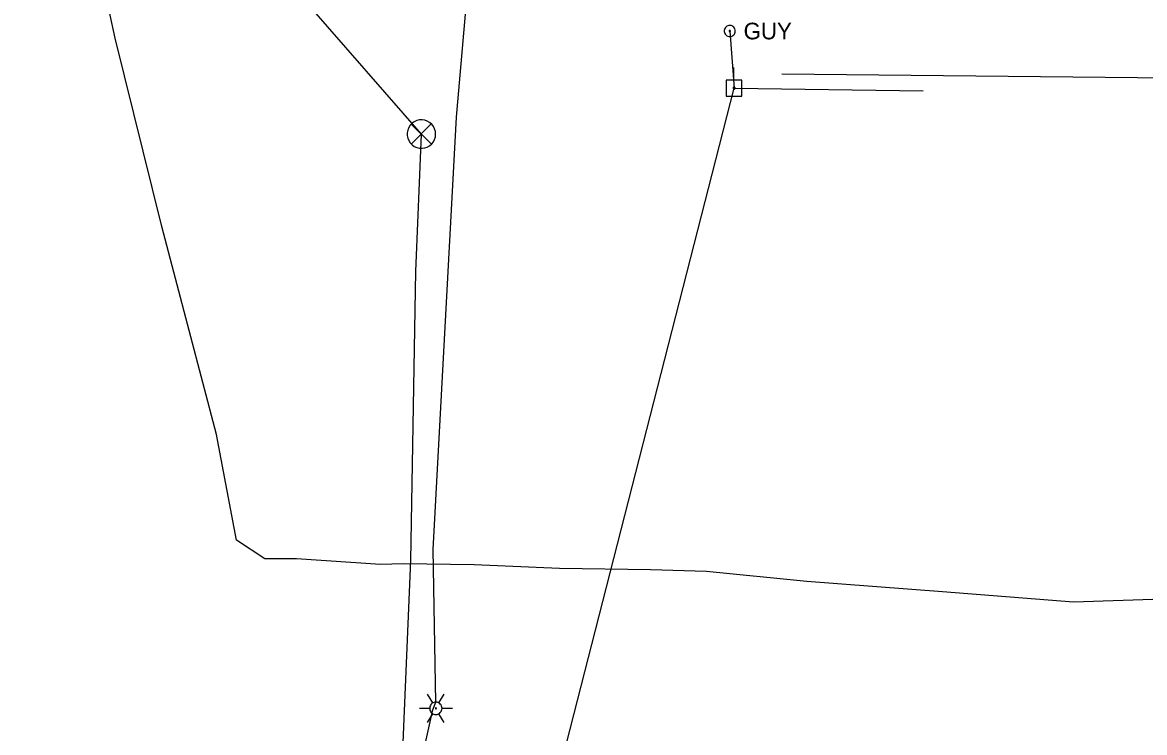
# Model space of a CAD drawing. Extents: x 596028 to 606371, y 330010 to 403088.
# Drawn here: x 604376.9 to 604636.4, y 338862.5 to 339026.7 of the extents above; entities that cross this region are included whole.
import ezdxf

# ---------------------------------------------------------------- set-up
doc = ezdxf.new("R2010")
doc.units = 0
for name, color, linetype in [('E_FTMS', 7, 'Continuous'), ('E_FTMS_Conduit', 7, 'Continuous'), ('E_LTG', 7, 'Continuous'), ('E_LTG_CID', 7, 'Continuous'), ('E_UTL_EGuyWire', 7, 'Continuous'), ('E_UTL_EPowerPole', 7, 'Continuous'), ('E_UTL_FO_UG_MWFN', 7, 'Continuous'), ('E_UTL_Overhead', 7, 'Continuous'), ('E_UTL_T_UG', 7, 'Continuous')]:
    doc.layers.add(name, color=color, linetype=linetype)

msp = doc.modelspace()

# ---------------------------------------------------------------- linework, layer by layer
at = {"layer": 'E_FTMS'}
for points in [[(604472.47, 339000.91), (604472.41, 339001.53), (604472.23, 339002.14), (604471.94, 339002.69), (604471.56, 339003.19), (604471.08, 339003.6), (604470.54, 339003.91), (604469.95, 339004.12), (604469.33, 339004.21), (604468.7, 339004.18), (604468.09, 339004.03), (604467.52, 339003.77), (604467.01, 339003.4), (604466.57, 339002.95), (604466.23, 339002.42), (604466, 339001.84), (604465.88, 339001.22), (604465.88, 339000.6), (604466, 338999.98), (604466.23, 338999.4), (604466.57, 338998.87), (604467.01, 338998.42), (604467.52, 338998.05), (604468.09, 338997.79), (604468.7, 338997.64), (604469.33, 338997.61), (604469.95, 338997.7), (604470.54, 338997.91), (604471.08, 338998.22), (604471.56, 338998.63), (604471.94, 338999.12), (604472.23, 338999.68), (604472.41, 339000.28), (604472.47, 339000.91)], [(604471.43, 339003.24), (604466.82, 338998.59)], [(604466.82, 339003.2), (604471.47, 338998.54)]]:
    msp.add_lwpolyline(points, dxfattribs=at)
at = {"layer": 'E_FTMS_Conduit'}
msp.add_lwpolyline([(604482.26, 338261.55), (604473.93, 338334.41), (604464.29, 338400.61), (604460.79, 338428.69), (604454.21, 338489.14), (604450.76, 338535.77), (604450.59, 338564.2), (604449.65, 338594.55), (604451.53, 338620.45), (604457.08, 338705.91), (604458.98, 338757.42), (604459.6, 338770.85), (604464.03, 338838.22), (604466.7, 338902.27), (604467.92, 338969.11), (604469.17, 339000.91), (604443.18, 339030.65), (604422.51, 339055.17), (604397.22, 339086.29), (604379.91, 339100.81)], dxfattribs=at)
at = {"layer": 'E_LTG'}
for points in [[(604471.8, 338869.35), (604470.61, 338871.41)], [(604473.23, 338869.35), (604474.42, 338871.41)], [(604468.71, 338868.11), (604471.09, 338868.11)], [(604473.95, 338868.11), (604473.92, 338868.38), (604473.84, 338868.64), (604473.72, 338868.88), (604473.55, 338869.09), (604473.35, 338869.27), (604473.11, 338869.41), (604472.85, 338869.5), (604472.59, 338869.54), (604472.31, 338869.52), (604472.05, 338869.46), (604471.8, 338869.35), (604471.58, 338869.19), (604471.39, 338868.99), (604471.25, 338868.76), (604471.15, 338868.51), (604471.1, 338868.24), (604471.1, 338867.97), (604471.15, 338867.71), (604471.25, 338867.45), (604471.39, 338867.22), (604471.58, 338867.03), (604471.8, 338866.87), (604472.05, 338866.76), (604472.31, 338866.69), (604472.59, 338866.68), (604472.85, 338866.72), (604473.11, 338866.81), (604473.35, 338866.94), (604473.55, 338867.12), (604473.72, 338867.34), (604473.84, 338867.58), (604473.92, 338867.84), (604473.95, 338868.11)], [(604473.95, 338868.11), (604473.92, 338868.38), (604473.84, 338868.64), (604473.72, 338868.88), (604473.55, 338869.09), (604473.35, 338869.27), (604473.11, 338869.41), (604472.85, 338869.5), (604472.59, 338869.54), (604472.31, 338869.52), (604472.05, 338869.46), (604471.8, 338869.35), (604471.58, 338869.19), (604471.39, 338868.99), (604471.25, 338868.76), (604471.15, 338868.51), (604471.1, 338868.24), (604471.1, 338867.97), (604471.15, 338867.71), (604471.25, 338867.45), (604471.39, 338867.22), (604471.58, 338867.03), (604471.8, 338866.87), (604472.05, 338866.76), (604472.31, 338866.69), (604472.59, 338866.68), (604472.85, 338866.72), (604473.11, 338866.81), (604473.35, 338866.94), (604473.55, 338867.12), (604473.72, 338867.34), (604473.84, 338867.58), (604473.92, 338867.84), (604473.95, 338868.11)], [(604473.95, 338868.11), (604473.92, 338868.38), (604473.84, 338868.64), (604473.72, 338868.88), (604473.55, 338869.09), (604473.35, 338869.27), (604473.11, 338869.41), (604472.85, 338869.5), (604472.59, 338869.54), (604472.31, 338869.52), (604472.05, 338869.46), (604471.8, 338869.35), (604471.58, 338869.19), (604471.39, 338868.99), (604471.25, 338868.76), (604471.15, 338868.51), (604471.1, 338868.24), (604471.1, 338867.97), (604471.15, 338867.71), (604471.25, 338867.45), (604471.39, 338867.22), (604471.58, 338867.03), (604471.8, 338866.87), (604472.05, 338866.76), (604472.31, 338866.69), (604472.59, 338866.68), (604472.85, 338866.72), (604473.11, 338866.81), (604473.35, 338866.94), (604473.55, 338867.12), (604473.72, 338867.34), (604473.84, 338867.58), (604473.92, 338867.84), (604473.95, 338868.11)], [(604472.64, 338868.11), (604472.63, 338868.13), (604472.63, 338868.15), (604472.62, 338868.17), (604472.6, 338868.19), (604472.59, 338868.21), (604472.57, 338868.22), (604472.55, 338868.22), (604472.52, 338868.23), (604472.5, 338868.23), (604472.48, 338868.22), (604472.46, 338868.21), (604472.44, 338868.2), (604472.42, 338868.18), (604472.41, 338868.16), (604472.4, 338868.14), (604472.4, 338868.12), (604472.4, 338868.1), (604472.4, 338868.07), (604472.41, 338868.05), (604472.42, 338868.03), (604472.44, 338868.02), (604472.46, 338868.01), (604472.48, 338868), (604472.5, 338867.99), (604472.52, 338867.99), (604472.55, 338867.99), (604472.57, 338868), (604472.59, 338868.01), (604472.6, 338868.03), (604472.62, 338868.04), (604472.63, 338868.06), (604472.63, 338868.09), (604472.64, 338868.11)], [(604473.95, 338868.11), (604476.33, 338868.11)], [(604470.61, 338864.81), (604471.8, 338866.87)], [(604474.42, 338864.81), (604473.23, 338866.87)]]:
    msp.add_lwpolyline(points, dxfattribs=at)
at = {"layer": 'E_LTG_CID'}
msp.add_lwpolyline([(604462.53, 338665.89), (604459.42, 338679.36), (604459.39, 338681.9), (604459.7, 338688.71), (604460.81, 338741.12), (604464.5, 338801.96), (604467.28, 338847.26), (604471.84, 338867.78), (604472.52, 338869.57), (604471.92, 338904.85), (604477.27, 339004.79), (604479.36, 339028.67), (604475.85, 339040.45), (604483.83, 339111.42), (604496.92, 339188.17), (604513.35, 339300.5)], dxfattribs=at)
at = {"layer": 'E_UTL_EGuyWire'}
msp.add_line((604540.49, 339024.73), (604541.5, 339011.54), dxfattribs=at)
for points in [[(604541.78, 339024.73), (604541.76, 339024.97), (604541.69, 339025.21), (604541.57, 339025.42), (604541.42, 339025.62), (604541.24, 339025.78), (604541.03, 339025.9), (604540.8, 339025.98), (604540.56, 339026.01), (604540.31, 339026), (604540.08, 339025.94), (604539.85, 339025.84), (604539.65, 339025.7), (604539.49, 339025.52), (604539.35, 339025.32), (604539.26, 339025.09), (604539.22, 339024.85), (604539.22, 339024.61), (604539.26, 339024.37), (604539.35, 339024.14), (604539.49, 339023.94), (604539.65, 339023.76), (604539.85, 339023.62), (604540.08, 339023.52), (604540.31, 339023.46), (604540.56, 339023.45), (604540.8, 339023.48), (604541.03, 339023.56), (604541.24, 339023.69), (604541.42, 339023.85), (604541.57, 339024.04), (604541.69, 339024.25), (604541.76, 339024.49), (604541.78, 339024.73)], [(604540.66, 339024.73), (604540.65, 339024.76), (604540.64, 339024.79), (604540.63, 339024.82), (604540.61, 339024.84), (604540.59, 339024.86), (604540.56, 339024.88), (604540.53, 339024.89), (604540.5, 339024.89), (604540.47, 339024.89), (604540.44, 339024.88), (604540.41, 339024.87), (604540.39, 339024.85), (604540.37, 339024.83), (604540.35, 339024.8), (604540.34, 339024.78), (604540.34, 339024.75), (604540.34, 339024.72), (604540.34, 339024.69), (604540.35, 339024.66), (604540.37, 339024.63), (604540.39, 339024.61), (604540.41, 339024.59), (604540.44, 339024.58), (604540.47, 339024.57), (604540.5, 339024.57), (604540.53, 339024.58), (604540.56, 339024.59), (604540.59, 339024.6), (604540.61, 339024.62), (604540.63, 339024.64), (604540.64, 339024.67), (604540.65, 339024.7), (604540.66, 339024.73)]]:
    msp.add_lwpolyline(points, dxfattribs=at)
at = {"layer": 'E_UTL_EPowerPole'}
for points in [[(604541.47, 339013.38), (604541.47, 339016.29)], [(604543.32, 339013.38), (604539.63, 339013.38)], [(604539.63, 339013.38), (604539.63, 339009.69)], [(604543.32, 339009.69), (604543.32, 339013.38)], [(604541.74, 339011.54), (604541.74, 339011.58), (604541.73, 339011.62), (604541.7, 339011.66), (604541.68, 339011.7), (604541.64, 339011.73), (604541.6, 339011.75), (604541.56, 339011.77), (604541.52, 339011.77), (604541.47, 339011.77), (604541.43, 339011.76), (604541.38, 339011.74), (604541.35, 339011.72), (604541.32, 339011.68), (604541.29, 339011.65), (604541.28, 339011.6), (604541.27, 339011.56), (604541.27, 339011.51), (604541.28, 339011.47), (604541.29, 339011.43), (604541.32, 339011.39), (604541.35, 339011.36), (604541.38, 339011.33), (604541.43, 339011.31), (604541.47, 339011.3), (604541.52, 339011.3), (604541.56, 339011.3), (604541.6, 339011.32), (604541.64, 339011.34), (604541.68, 339011.37), (604541.7, 339011.41), (604541.73, 339011.45), (604541.74, 339011.49), (604541.74, 339011.54)], [(604539.63, 339009.69), (604543.32, 339009.69)]]:
    msp.add_lwpolyline(points, dxfattribs=at)
at = {"layer": 'E_UTL_FO_UG_MWFN'}
msp.add_lwpolyline([(604668.86, 338889.96), (604662.95, 338891.55), (604654.46, 338893.67), (604640.66, 338893.37), (604620.04, 338892.68), (604589.67, 338895.03), (604558.3, 338897.41), (604535.11, 338899.73), (604522.19, 338900.1), (604501.1, 338900.47), (604481.36, 338901.26), (604464.99, 338901.5), (604459.7, 338901.38), (604440.3, 338902.67), (604432.93, 338902.67), (604426.37, 338907.02), (604421.8, 338931.44), (604409.13, 338979.56), (604398.32, 339023.06), (604393.6, 339044.86), (604389.81, 339059.44), (604379.58, 339083.75), (604376.89, 339101.68), (604380.04, 339106.11)], dxfattribs=at)
at = {"layer": 'E_UTL_Overhead'}
for p, q in [((604484.36, 338788.16), (604541.5, 339011.54)), ((604541.5, 339011.54), (604585.27, 339010.92))]:
    msp.add_line(p, q, dxfattribs=at)
at = {"layer": 'E_UTL_T_UG'}
msp.add_line((604552.53, 339014.82), (604801.15, 339012.35), dxfattribs=at)

# ---------------------------------------------------------------- texts
at = {"layer": 'E_UTL_EGuyWire'}
msp.add_text('GUY', height=3.85, dxfattribs=at).set_placement((604543.7, 339022.81))

doc.saveas('drawing.dxf')
